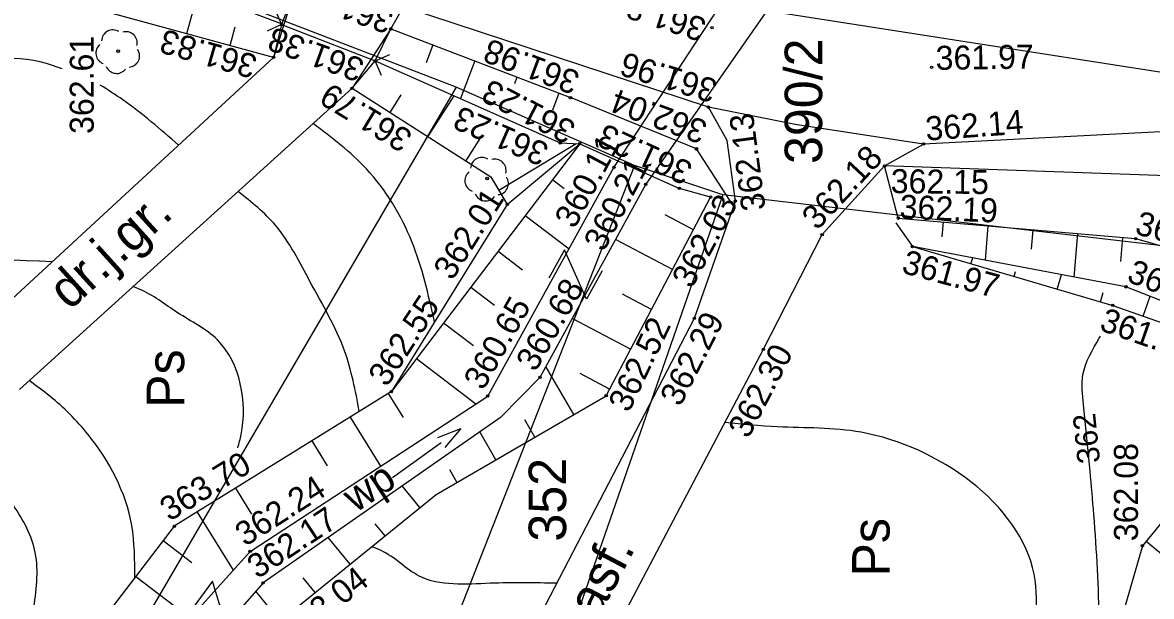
# Model space of a CAD drawing. Extents: x 4635329 to 4651863, y 5356628 to 5367582.
# Drawn here: x 4651155.45 to 4651193.08, y 5356669.94 to 5356689.07 of the extents above; entities that cross this region are included whole.
import ezdxf

# ---------------------------------------------------------------- set-up
doc = ezdxf.new("R2010")
doc.units = 0
for name, color, linetype in [('Level 12', 7, 'Continuous'), ('Level 20', 7, 'Continuous'), ('Level 21', 7, 'Continuous'), ('Level 22', 7, 'Continuous'), ('Level 24', 7, 'Continuous'), ('Level 29', 7, 'Continuous'), ('Level 4', 7, 'Continuous'), ('Level 44', 7, 'Continuous'), ('Level 45', 7, 'Continuous'), ('Level 46', 7, 'Continuous'), ('Level 47', 7, 'Continuous'), ('Level 48', 7, 'Continuous'), ('Level 5', 7, 'Continuous'), ('Level 50', 7, 'Continuous'), ('Level 51', 7, 'Continuous'), ('Level 53', 7, 'Continuous'), ('Level 55', 7, 'Continuous')]:
    doc.layers.add(name, color=color, linetype=linetype)

msp = doc.modelspace()

# ---------------------------------------------------------------- linework, layer by layer
at = {"layer": 'Level 20'}
for points in [[(4651201.455, 5356686.167), (4651194.035, 5356685.457), (4651185.485, 5356685.017), (4651181.21, 5356685.664), (4651178.315, 5356686.247), (4651168.145, 5356689.587), (4651157.765, 5356693.687), (4651144.895, 5356698.917), (4651120.155, 5356708.837)], [(4651164.505, 5356690.097), (4651163.815, 5356687.907), (4651153.195, 5356678.107)], [(4651167.725, 5356688.857), (4651168.145, 5356689.587)], [(4651167.725, 5356688.857), (4651166.435, 5356686.877), (4651155.343, 5356676.839)], [(4651168.395, 5356660.997), (4651177.845, 5356679.207), (4651179.215, 5356683.117), (4651178.934, 5356685.139), (4651178.315, 5356686.247)], [(4651170.485, 5356659.807), (4651180.145, 5356678.177), (4651182.105, 5356681.997), (4651184.185, 5356684.287), (4651185.485, 5356685.017)]]:
    msp.add_lwpolyline(points, dxfattribs=at)
at = {"layer": 'Level 22'}
for points in [[(4651175.165, 5356684.237), (4651181.115, 5356693.317)], [(4651182.615, 5356692.847), (4651176.225, 5356683.677)]]:
    msp.add_lwpolyline(points, dxfattribs=at)
at = {"layer": 'Level 24'}
for p, q in [((4651163.871, 5356689.482), (4651164.085, 5356688.997)), ((4651164.085, 5356688.997), (4651163.6, 5356688.783)), ((4651164.085, 5356688.997), (4651167.205, 5356687.787)), ((4651167.205, 5356687.787), (4651167.69, 5356688.001)), ((4651167.419, 5356687.302), (4651167.205, 5356687.787))]:
    msp.add_line(p, q, dxfattribs=at)
at = {"layer": 'Level 29'}
msp.add_line((4651174.025, 5356685.027), (4651177.345, 5356683.537), dxfattribs=at)
at = {"layer": 'Level 4'}
for p, q in [((4651169.904, 5356686.914), (4651125.563, 5356703.993)), ((4651206.08, 5356685.424), (4651174.835, 5356690.307)), ((4651169.904, 5356686.914), (4651156.863, 5356664.599)), ((4651175.849, 5356684.307), (4651169.904, 5356686.914)), ((4651175.849, 5356684.307), (4651166.932, 5356661.628)), ((4651178.797, 5356683.326), (4651175.849, 5356684.307)), ((4651178.797, 5356683.326), (4651170.632, 5356659.869)), ((4651197.109, 5356681.204), (4651178.797, 5356683.326))]:
    msp.add_line(p, q, dxfattribs=at)
at = {"layer": 'Level 44'}
for centre in [(4651164.085, 5356688.997), (4651178.435, 5356688.897), (4651167.725, 5356688.857), (4651158.635, 5356688.117), (4651163.815, 5356687.907), (4651167.205, 5356687.787), (4651185.755, 5356687.577), (4651166.435, 5356686.877), (4651173.715, 5356686.567), (4651178.315, 5356686.247), (4651173.375, 5356685.057), (4651174.025, 5356685.027), (4651177.915, 5356684.857), (4651185.485, 5356685.017), (4651175.165, 5356684.237), (4651184.185, 5356684.287), (4651170.935, 5356683.867), (4651176.225, 5356683.677), (4651177.345, 5356683.537), (4651178.385, 5356683.247), (4651171.605, 5356683.007), (4651179.215, 5356683.117), (4651184.645, 5356682.547), (4651182.105, 5356681.997), (4651192.555, 5356681.867), (4651185.115, 5356681.597), (4651192.235, 5356680.257), (4651191.795, 5356679.637), (4651177.845, 5356679.207), (4651180.145, 5356678.177), (4651172.695, 5356677.237), (4651167.745, 5356676.767), (4651170.955, 5356676.617), (4651174.905, 5356676.627), (4651160.505, 5356672.277), (4651192.785, 5356671.627), (4651163.035, 5356671.437), (4651163.465, 5356670.387)]:
    msp.add_circle(centre, 0.04, dxfattribs=at)
at = {"layer": 'Level 46'}
msp.add_line((4651191.037, 5356674.114), (4651190.821, 5356676.325), dxfattribs=at)
for points in [[(4651156.765, 5356687.524), (4651156.246, 5356687.701), (4651149.028, 5356687.58), (4651145.813, 5356689.823), (4651143.266, 5356691.036), (4651138.778, 5356692.066), (4651136.17, 5356693.037), (4651136.124, 5356693.062)], [(4651160.643, 5356684.98), (4651158.793, 5356686.488), (4651158.034, 5356686.985)], [(4651169.182, 5356679.091), (4651168.427, 5356681.764), (4651166.91, 5356684.19), (4651165.131, 5356685.698)], [(4651166.674, 5356676.103), (4651166.182, 5356678.126), (4651165.03, 5356680.43), (4651163.878, 5356682.31), (4651162.632, 5356683.436)], [(4651156.433, 5356681.095), (4651149.756, 5356681.88), (4651146.786, 5356683.038)], [(4651162.625, 5356674.888), (4651162.736, 5356675.332), (4651161.947, 5356678.485), (4651160.613, 5356679.394), (4651159.339, 5356680.182), (4651159.127, 5356680.264)], [(4651190.821, 5356676.325), (4651190.8, 5356677.331), (4651191.346, 5356678.543), (4651191.386, 5356678.609)], [(4651159.189, 5356670.554), (4651159.086, 5356672.305), (4651157.63, 5356675.337), (4651156.357, 5356676.61), (4651155.664, 5356677.13)], [(4651186.942, 5356655.734), (4651186.443, 5356658.066), (4651187.231, 5356661.219), (4651188.565, 5356664.25), (4651188.99, 5356667.342), (4651189.172, 5356670.677), (4651183.41, 5356675.407), (4651180.62, 5356675.589), (4651178.861, 5356675.735)], [(4651155.447, 5356666.303), (4651155.811, 5356669.456), (4651155.871, 5356671.396), (4651155.144, 5356672.972), (4651154.276, 5356674.106)], [(4651191.346, 5356666.645), (4651191.346, 5356669.024), (4651191.164, 5356672.662), (4651191.037, 5356674.114)], [(4651173.261, 5356670.374), (4651171.037, 5356670.374), (4651168.672, 5356670.617), (4651167.398, 5356671.466), (4651167.084, 5356671.591)]]:
    msp.add_spline(points, degree=3, dxfattribs=at)
at = {"layer": 'Level 48'}
for p, q in [((4651160.921, 5356688.699), (4651161.299, 5356690.077)), ((4651162.368, 5356688.303), (4651162.538, 5356688.924)), ((4651169.126, 5356688.321), (4651168.9, 5356687.729)), ((4651170.527, 5356687.786), (4651170.047, 5356686.53)), ((4651171.928, 5356687.25), (4651171.843, 5356687.029)), ((4651167.698, 5356686.068), (4651168.073, 5356686.653)), ((4651173.329, 5356686.714), (4651173.113, 5356686.149)), ((4651168.962, 5356685.26), (4651169.835, 5356686.623)), ((4651170.225, 5356684.451), (4651170.724, 5356685.23)), ((4651171.321, 5356683.479), (4651173.9, 5356685.033)), ((4651173.117, 5356683.833), (4651173.504, 5356683.539)), ((4651172.209, 5356682.639), (4651173.669, 5356681.529)), ((4651177.813, 5356682.159), (4651176.873, 5356682.653)), ((4651186.139, 5356682.419), (4651186.097, 5356681.919)), ((4651187.634, 5356682.29), (4651187.535, 5356681.141)), ((4651189.128, 5356682.162), (4651189.073, 5356681.512)), ((4651177.115, 5356680.831), (4651175.213, 5356681.831)), ((4651190.623, 5356682.033), (4651190.498, 5356680.584)), ((4651192.117, 5356681.905), (4651192.049, 5356681.105)), ((4651171.301, 5356681.445), (4651172.119, 5356680.823)), ((4651185.628, 5356681.447), (4651185.635, 5356681.472)), ((4651187.067, 5356681.024), (4651187.124, 5356681.219)), ((4651188.506, 5356680.602), (4651188.556, 5356680.771)), ((4651189.945, 5356680.18), (4651190.087, 5356680.661)), ((4651170.394, 5356680.251), (4651171.184, 5356679.65)), ((4651176.417, 5356679.503), (4651175.454, 5356680.009)), ((4651191.385, 5356679.757), (4651191.477, 5356680.07)), ((4651192.807, 5356679.281), (4651193.039, 5356679.941)), ((4651175.719, 5356678.176), (4651173.771, 5356679.2)), ((4651169.486, 5356679.057), (4651170.478, 5356678.303)), ((4651168.578, 5356677.863), (4651170.558, 5356676.357)), ((4651173.823, 5356675.999), (4651172.894, 5356677.601)), ((4651175.021, 5356676.848), (4651174.035, 5356677.366)), ((4651167.64, 5356676.702), (4651168.137, 5356675.9)), ((4651166.365, 5356675.911), (4651167.378, 5356674.278)), ((4651172.526, 5356675.247), (4651172.194, 5356675.819)), ((4651171.228, 5356674.494), (4651170.69, 5356675.422)), ((4651165.09, 5356675.121), (4651165.606, 5356674.289)), ((4651169.931, 5356673.741), (4651169.693, 5356674.151)), ((4651162.541, 5356673.54), (4651163.076, 5356672.677)), ((4651168.695, 5356672.899), (4651168.108, 5356673.623)), ((4651161.266, 5356672.749), (4651162.469, 5356670.808)), ((4651167.531, 5356671.954), (4651167.202, 5356672.358)), ((4651160.138, 5356671.797), (4651161.092, 5356671.068)), ((4651166.366, 5356671.008), (4651165.64, 5356671.903)), ((4651192.905, 5356671.773), (4651196.255, 5356669.031)), ((4651159.227, 5356670.605), (4651161.04, 5356669.22)), ((4651165.202, 5356670.063), (4651164.804, 5356670.553)), ((4651164.037, 5356669.117), (4651163.227, 5356670.115))]:
    msp.add_line(p, q, dxfattribs=at)
for points in [[(4651119.395, 5356706.647), (4651144.585, 5356696.527), (4651156.915, 5356691.727), (4651164.127, 5356689.012)], [(4651163.815, 5356687.907), (4651156.325, 5356689.957), (4651143.745, 5356694.647), (4651136.825, 5356697.727), (4651118.775, 5356705.457)], [(4651164.505, 5356690.097), (4651164.085, 5356688.997), (4651163.815, 5356687.907)], [(4651166.435, 5356686.877), (4651167.205, 5356687.787), (4651167.725, 5356688.857)], [(4651167.725, 5356688.857), (4651173.715, 5356686.567)], [(4651167.205, 5356687.787), (4651173.375, 5356685.057), (4651174.025, 5356685.027)], [(4651166.435, 5356686.877), (4651171.055, 5356683.92), (4651171.605, 5356683.007), (4651167.745, 5356676.767)], [(4651179.135, 5356682.97), (4651177.915, 5356684.857), (4651173.715, 5356686.567)], [(4651184.645, 5356682.547), (4651192.555, 5356681.867), (4651198.855, 5356680.077), (4651203.865, 5356685.737)], [(4651174.025, 5356685.027), (4651167.745, 5356676.767), (4651160.505, 5356672.277), (4651156.105, 5356666.517)], [(4651171.605, 5356683.007), (4651174.025, 5356685.027)], [(4651193.935, 5356683.947), (4651184.185, 5356684.287)], [(4651184.645, 5356682.547), (4651184.185, 5356684.287)], [(4651178.385, 5356683.247), (4651177.345, 5356683.537)], [(4651162.025, 5356663.467), (4651164.025, 5356669.107), (4651169.234, 5356673.337), (4651174.905, 5356676.627), (4651178.385, 5356683.247)], [(4651184.565, 5356682.391), (4651185.115, 5356681.597), (4651191.795, 5356679.637), (4651197.655, 5356677.577)], [(4651198.515, 5356677.787), (4651192.235, 5356680.257), (4651185.115, 5356681.597)], [(4651197.655, 5356677.577), (4651192.785, 5356671.627), (4651190.685, 5356664.357), (4651184.035, 5356649.037), (4651181.425, 5356636.777)]]:
    msp.add_lwpolyline(points, dxfattribs=at)
at = {"layer": 'Level 50'}
for p, q in [((4651169.288, 5356675.232), (4651170.054, 5356675.536)), ((4651170.054, 5356675.536), (4651169.521, 5356674.906)), ((4651167.78, 5356673.903), (4651169.405, 5356675.069))]:
    msp.add_line(p, q, dxfattribs=at)
for points in [[(4651157.745, 5356665.536), (4651158.355, 5356666.237), (4651163.035, 5356671.437), (4651170.955, 5356676.617), (4651175.165, 5356684.237)], [(4651176.225, 5356683.677), (4651172.695, 5356677.237), (4651171.383, 5356675.905), (4651163.465, 5356670.387), (4651158.425, 5356664.617)]]:
    msp.add_lwpolyline(points, dxfattribs=at)
at = {"layer": 'Level 53'}
for p, q in [((4651173.513, 5356681.487), (4651172.988, 5356680.543)), ((4651174.246, 5356679.845), (4651173.513, 5356681.487)), ((4651174.771, 5356680.788), (4651174.246, 5356679.845)), ((4651161.774, 5356670.442), (4651161.137, 5356669.57)), ((4651162.3, 5356668.722), (4651161.774, 5356670.442))]:
    msp.add_line(p, q, dxfattribs=at)
at = {"layer": 'Level 55'}
for centre in [(4651158.635, 5356688.117), (4651170.935, 5356683.867)]:
    msp.add_circle(centre, 0.045, dxfattribs=at)
for centre, start, end in [((4651158.457, 5356688.447), 58.348, 178.132), ((4651158.894, 5356688.388), 346.3906, 106.042), ((4651158.266, 5356688.05), 130.3488, 250.1306), ((4651158.973, 5356687.954), 274.3875, 34.0933), ((4651158.585, 5356687.746), 202.4389, 322.0902), ((4651170.757, 5356684.197), 58.348, 178.132), ((4651171.194, 5356684.138), 346.3906, 106.042), ((4651170.566, 5356683.8), 130.3488, 250.1306), ((4651171.273, 5356683.704), 274.3875, 34.0933), ((4651170.885, 5356683.496), 202.4389, 322.0902)]:
    msp.add_arc(centre, 0.375, start, end, dxfattribs=at)

# ---------------------------------------------------------------- texts
at = {"layer": 'Level 12'}
for p in [(4651160.835, 5356676.22), (4651184.354, 5356670.598)]:
    msp.add_text('Ps', height=1.25, rotation=90, dxfattribs=at).set_placement(p)
at = {"layer": 'Level 21'}
for s, rotation, p in [('dr.j.gr.', 42.1444, (4651157.013, 5356679.449)), ('dr.j.asf. ', 62.262, (4651173.339, 5356666.695))]:
    msp.add_text(s, height=1.25, rotation=rotation, dxfattribs=at).set_placement(p)
at = {"layer": 'Level 45'}
for s, rotation, p in [('361.88', 160.5879, (4651167.87, 5356689.425)), ('361.84', 161.8643, (4651178.297, 5356689.173)), ('362.61', 90, (4651157.82, 5356685.353)), ('361.83', 163.9909, (4651163.32, 5356687.955)), ('361.38', 159.9704, (4651166.895, 5356687.817)), ('361.98', 159.4106, (4651174.08, 5356687.394)), ('361.97', 0.8137, (4651185.894, 5356687.488)), ('361.96', 162.9616, (4651178.664, 5356687.137)), ('361.23', 152.6767, (4651173.95, 5356685.7)), ('361.79', 148.7114, (4651168.5, 5356685.384)), ('362.04', 160.0091, (4651178.331, 5356685.752)), ('361.23', 156.2938, (4651173.047, 5356684.989)), ('362.13', 97.473, (4651180.222, 5356682.843)), ('362.14', 4.0999, (4651185.575, 5356685.13)), ('361.23', 155.3135, (4651177.845, 5356684.352)), ('360.11', 61.923, (4651173.851, 5356682.161)), ('362.18', 46.9859, (4651181.941, 5356682.113)), ('360.21', 62.3832, (4651174.826, 5356681.396)), ('362.15', 359.4066, (4651184.389, 5356683.382)), ('362.01', 57.5579, (4651169.772, 5356680.435)), ('362.03', 61.6199, (4651177.759, 5356680.169)), ('362.19', 357.6067, (4651184.676, 5356682.533)), ('362.30', 344.8169, (4651192.498, 5356682.028)), ('361.97', 344.7593, (4651184.721, 5356680.733)), ('361.49', 338.2685, (4651192.224, 5356680.454)), ('360.68', 59.8623, (4651172.546, 5356677.39)), ('362.55', 56.9076, (4651167.594, 5356676.887)), ('360.65', 60.4953, (4651170.806, 5356676.772)), ('361.89', 340.4583, (4651191.313, 5356678.824)), ('362.52', 64.282, (4651175.663, 5356676.034)), ('362.29', 62.9292, (4651177.374, 5356676.232)), ('362.30', 62.3867, (4651179.643, 5356675.166)), ('362.08', 90, (4651192.635, 5356671.777)), ('363.70', 31.4673, (4651160.346, 5356672.42)), ('362.24', 32.5528, (4651162.868, 5356671.581)), ('362.17', 33.2936, (4651163.278, 5356670.503)), ('363.04', 38.461, (4651164.49, 5356668.328))]:
    msp.add_text(s, height=0.8, rotation=rotation, dxfattribs=at).set_placement(p)
at = {"layer": 'Level 47'}
msp.add_text('362', height=0.75, rotation=95.9966, dxfattribs=at).set_placement((4651191.377, 5356674.407))
at = {"layer": 'Level 5'}
for s, p in [('390/2', (4651182.106, 5356684.352)), ('352', (4651173.57, 5356671.765))]:
    msp.add_text(s, height=1.25, rotation=90, dxfattribs=at).set_placement(p)
at = {"layer": 'Level 51'}
msp.add_text('wp', height=1, rotation=33.5081, dxfattribs=at).set_placement((4651166.55, 5356672.708))

doc.saveas('drawing.dxf')
